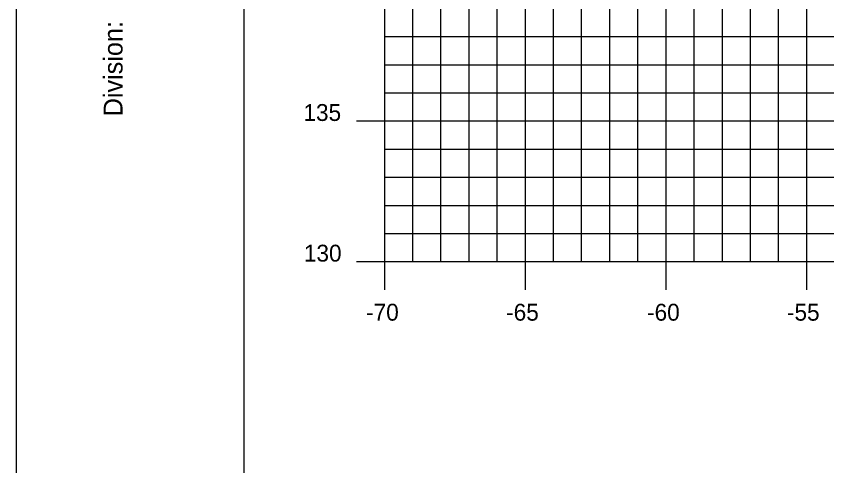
# Model space of a CAD drawing. Extents: x 1146746 to 1146916, y 608981 to 609091.
# Drawn here: x 1146746.33 to 1146775.14, y 609013.08 to 609029.06 of the extents above; entities that cross this region are included whole.
import ezdxf

# ---------------------------------------------------------------- set-up
doc = ezdxf.new("R2010")
doc.units = 0
for name, color, linetype in [('BORDER', 7, 'Continuous'), ('H_V ANNOTATION', 7, 'Continuous'), ('MAJOR', 7, 'Continuous'), ('MINOR', 7, 'Continuous'), ('PLOT BOUNDARY', 7, 'Continuous')]:
    doc.layers.add(name, color=color, linetype=linetype)

msp = doc.modelspace()

# ---------------------------------------------------------------- linework, layer by layer
at = {"layer": 'BORDER'}
msp.add_lwpolyline([(1146754.428, 608984.335), (1146914.428, 608984.335), (1146914.428, 609089.335), (1146754.428, 609089.335)], close=True, dxfattribs=at)
at = {"layer": 'MAJOR'}
for p, q in [((1146759.428, 609020.335), (1146759.428, 609040.335)), ((1146759.428, 609020.335), (1146759.428, 609040.335)), ((1146764.428, 609020.335), (1146764.428, 609040.335)), ((1146769.428, 609020.335), (1146769.428, 609040.335)), ((1146774.428, 609020.335), (1146774.428, 609040.335)), ((1146758.426, 609025.335), (1146759.428, 609025.335)), ((1146759.428, 609025.335), (1146899.428, 609025.335)), ((1146758.426, 609020.335), (1146759.428, 609020.335)), ((1146759.428, 609020.335), (1146899.428, 609020.335)), ((1146759.428, 609020.335), (1146899.428, 609020.335)), ((1146759.428, 609019.333), (1146759.428, 609020.335)), ((1146764.428, 609019.333), (1146764.428, 609020.335)), ((1146769.428, 609019.333), (1146769.428, 609020.335)), ((1146774.428, 609019.333), (1146774.428, 609020.335))]:
    msp.add_line(p, q, dxfattribs=at)
at = {"layer": 'MINOR'}
for p, q in [((1146760.428, 609020.335), (1146760.428, 609040.335)), ((1146761.428, 609020.335), (1146761.428, 609040.335)), ((1146762.428, 609020.335), (1146762.428, 609040.335)), ((1146763.428, 609020.335), (1146763.428, 609040.335)), ((1146765.428, 609020.335), (1146765.428, 609040.335)), ((1146766.428, 609020.335), (1146766.428, 609040.335)), ((1146767.428, 609020.335), (1146767.428, 609040.335)), ((1146768.428, 609020.335), (1146768.428, 609040.335)), ((1146770.428, 609020.335), (1146770.428, 609040.335)), ((1146771.428, 609020.335), (1146771.428, 609040.335)), ((1146772.428, 609020.335), (1146772.428, 609040.335)), ((1146773.428, 609020.335), (1146773.428, 609040.335)), ((1146759.428, 609028.335), (1146899.428, 609028.335)), ((1146759.428, 609028.335), (1146760.43, 609028.335)), ((1146759.428, 609027.335), (1146899.428, 609027.335)), ((1146759.428, 609027.335), (1146760.43, 609027.335)), ((1146759.428, 609026.335), (1146899.428, 609026.335)), ((1146759.428, 609026.335), (1146760.43, 609026.335)), ((1146759.428, 609024.335), (1146899.428, 609024.335)), ((1146759.428, 609024.335), (1146760.43, 609024.335)), ((1146759.428, 609023.335), (1146899.428, 609023.335)), ((1146759.428, 609023.335), (1146760.43, 609023.335)), ((1146759.428, 609022.335), (1146899.428, 609022.335)), ((1146759.428, 609022.335), (1146760.43, 609022.335)), ((1146759.428, 609021.335), (1146899.428, 609021.335)), ((1146759.428, 609021.335), (1146760.43, 609021.335))]:
    msp.add_line(p, q, dxfattribs=at)
at = {"layer": 'PLOT BOUNDARY'}
msp.add_lwpolyline([(1146746.335, 608981.276), (1146916.335, 608981.276), (1146916.335, 609091.276), (1146746.335, 609091.276)], close=True, dxfattribs=at)

# ---------------------------------------------------------------- texts
at = {"layer": 'BORDER'}
msp.add_text('Division:', height=0.6696, rotation=90, dxfattribs=at).set_placement((1146750.113, 609025.501))
at = {"layer": 'H_V ANNOTATION'}
for s, p in [('135', (1146756.542, 609025.335)), ('130', (1146756.558, 609020.335)), ('-70', (1146758.769, 609018.235)), ('-65', (1146763.745, 609018.235)), ('-60', (1146768.753, 609018.235)), ('-55', (1146773.724, 609018.235))]:
    msp.add_text(s, height=0.6, dxfattribs=at).set_placement(p)
at = {"layer": 'MAJOR'}
msp.add_text('-', height=0.006, dxfattribs=at).set_placement((1146759.423, 609020.335))

doc.saveas('drawing.dxf')
